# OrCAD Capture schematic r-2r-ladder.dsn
size A; title: R-2R Ladder
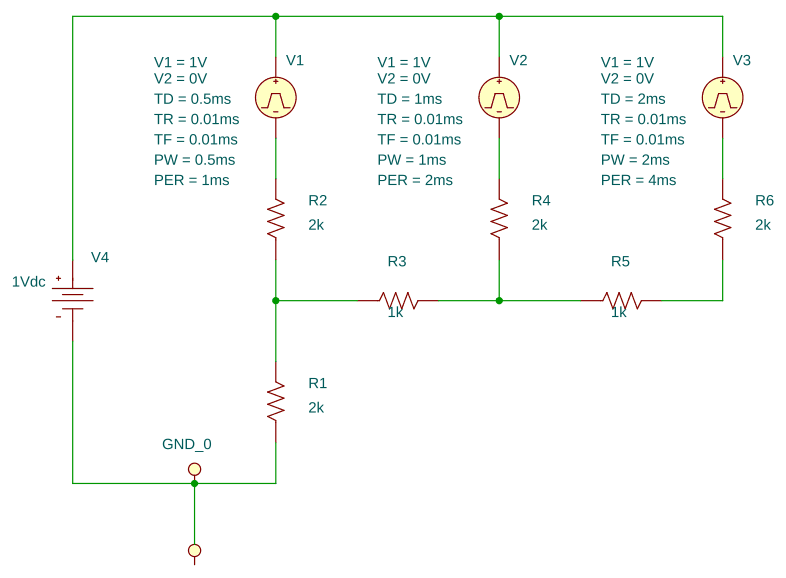
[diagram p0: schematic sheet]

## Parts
R1  2k  [AXRC05]
R2  2k  [AXRC05]
R3  1k  [AXRC05]
R4  2k  [AXRC05]
R5  1k  [AXRC05]
R6  2k  [AXRC05]
V1  VPULSE
V2  VPULSE
V3  VPULSE
V4  VDC

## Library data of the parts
R1-R6 = R
V1 = VPULSE: PER: 1ms; PW: 0.5ms; TD: 0.5ms; TF: 0.01ms; TR: 0.01ms; V1: 1V; V2: 0V
V2 = VPULSE: PER: 2ms; PW: 1ms; TD: 1ms; TF: 0.01ms; TR: 0.01ms; V1: 1V; V2: 0V
V3 = VPULSE: PER: 4ms; PW: 2ms; TD: 2ms; TF: 0.01ms; TR: 0.01ms; V1: 1V; V2: 0V
V4 = VDC: DC: 1Vdc

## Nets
0: R1.1 V4.1(-)
N14448: R1.2 R2.1 R3.1
N14473: R3.2 R4.1 R5.1
N14477: R5.2 R6.1
N14498: R6.2 V3.2(-)
N14503: R4.2 V2.2(-)
N14520: R2.2 V1.2(-)
N14769: V1.1(+) V2.1(+) V3.1(+) V4.0(+)
